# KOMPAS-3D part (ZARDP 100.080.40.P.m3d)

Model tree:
1. Булева операция:1
2. Булева операция:2
3. Булева операция:3
4. Булева операция:4
5. Булева операция:5
6. Булева операция:6
7. Булева операция:7
8. Булева операция:8
9. Булева операция:9
10. Булева операция:10
11. Булева операция:11
12. Булева операция:12
13. Булева операция:13
14. Булева операция:14
15. Булева операция:15
16. Булева операция:16
17. Булева операция:17
18. Булева операция:18
19. Булева операция:19
20. Булева операция:20
21. Булева операция:21
22. Булева операция:22
23. Булева операция:23
24. Булева операция:24
25. Булева операция:25
26. Булева операция:26
27. Булева операция:27
28. Булева операция:28
29. Булева операция:29
30. Булева операция:30
31. Булева операция:31
32. Булева операция:32
33. Булева операция:33
34. Булева операция:34
35. Булева операция:35
36. Булева операция:36
37. Булева операция:37
38. Булева операция:38
39. Булева операция:39
40. Булева операция:40
41. Булева операция:41
42. Булева операция:42
43. Булева операция:43
44. Булева операция:44
45. Булева операция:45
46. Булева операция:46
47. Булева операция:47
48. Булева операция:48
49. Булева операция:49
50. Булева операция:50
51. Булева операция:51
